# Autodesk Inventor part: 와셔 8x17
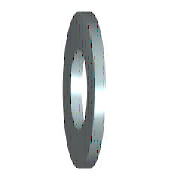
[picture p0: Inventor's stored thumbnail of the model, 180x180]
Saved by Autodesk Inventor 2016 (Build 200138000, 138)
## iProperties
Created: 2012-02
Part Number: 와셔 8x17
Material: 강철, 연강
Description: 평면 와셔
Document SubType Name: Modeling
Standard: KS B 1326
Designer: mduedu
Standards Organization: KS
Language: ko-KR
Size Designation: 8x17
Categories: <MemberInstance><Categories><Category DisplayName="조임쇠" InternalName="e4da775c-781d-43d5-af7c-5136215cf5a6" Mnemonic="FSTN"><Category DisplayName="와셔" InternalN
Density: 1 g/cm^3
Appearance: 주황색
IsCustomPart: 1
Author: mduedu
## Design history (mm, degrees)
sketch "스케치"
  geometry: C1 r 8.5 at (0, 0); C2 r 4.2 at (0, 0); 1 further point
  constraints: 2 centre point, 2 coincident
  dimensions: "d0" = 8.4 diameter of C2 (= SD1); "d1" = 17 diameter of C1 (= SD2)
extrude "본체" new body sketch "스케치" distance "d2" = 1.6 (= SD); taper "d3" = 0 deg
workaxis "Work Axis1"
workplane "Work Plane1"
body "Solid1"
other parameters: "SD1" = 8.4 [user parameter; used in 1 equation term], "SD2" = 17 [user parameter; used in 1 equation term], "SD" = 1.6 [user parameter; used in 1 equation term], "d4" = 0, "d5" = 0, "d6" = 0, "d7" = 0, "NND" = 8 [user parameter]
